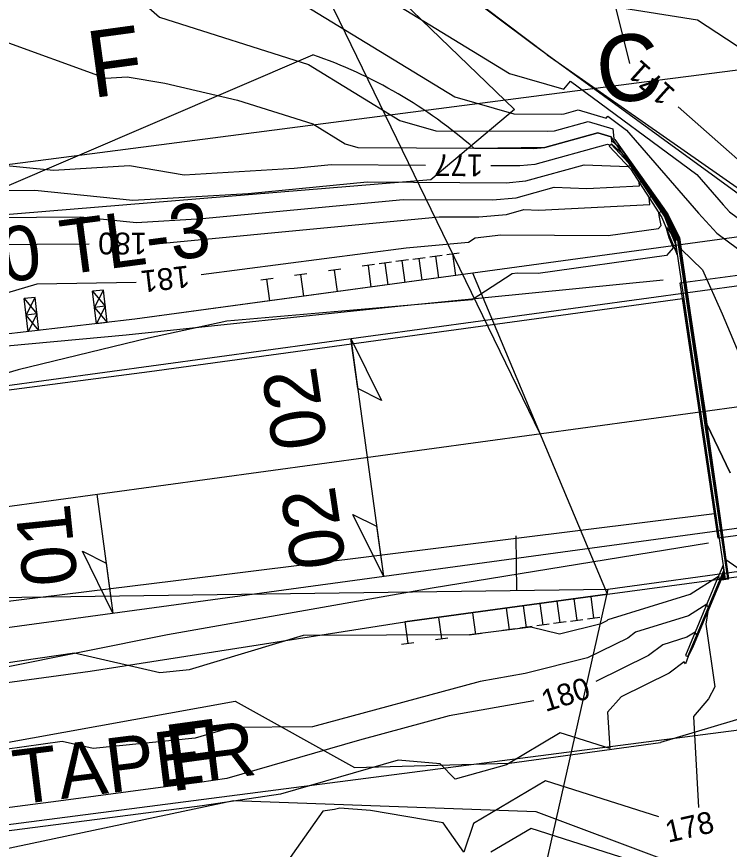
# Model space of a CAD drawing. Extents: x 2086416 to 2115205, y 575507 to 632762.
# Drawn here: x 2111454.1 to 2111519.4, y 581610 to 581686.3 of the extents above; entities that cross this region are included whole.
import ezdxf

# ---------------------------------------------------------------- set-up
doc = ezdxf.new("R2010")
doc.units = 0
for name, color, linetype in [('Default', 7, 'Continuous'), ('DTM Contours Major', 7, 'Continuous'), ('DTM Contours Major Text', 7, 'Continuous'), ('DTM Contours Minor', 7, 'Continuous'), ('DTM Contours Minor Text', 7, 'Continuous'), ('Exist Guardrail', 7, 'Continuous'), ('Exist Hydro Stream or Body of Water', 7, 'Continuous'), ('Exist Right of Way Line', 7, 'Continuous'), ('Exist Roads EOP', 7, 'Continuous'), ('Exist Structure Major Bridge WW', 7, 'Continuous'), ('Exist Structure Major Deck Tunnel Box Culvert', 7, 'Continuous'), ('Exist Vegetation Woods Line', 7, 'Continuous'), ('Prop Horizontal Alignment', 7, 'Continuous'), ('Prop Horizontal Alignment Station Label', 7, 'Continuous'), ('Prop Roadway Bridge', 7, 'Continuous'), ('Prop SS Cut Line', 7, 'Continuous'), ('Prop SS Cut Text', 7, 'Continuous'), ('Prop SS Fill Line', 7, 'Continuous'), ('Prop SS Fill Text', 7, 'Continuous')]:
    doc.layers.add(name, color=color, linetype=linetype)

msp = doc.modelspace()

# ---------------------------------------------------------------- linework, layer by layer
at = {"layer": 'Default'}
for p, q in [((2111430.061, 581649.328), (2112312.029, 581769.688)), ((2111433.036, 581627.53), (2112315.004, 581747.89)), ((2111508.232, 581633.802), (2112048.04, 581707.887)), ((2111493.061, 581664.401), (2111491.926, 581664.246)), ((2111492.764, 581662.342), (2111492.494, 581664.324)), ((2111494.609, 581664.613), (2111493.474, 581664.458)), ((2111494.312, 581662.553), (2111494.042, 581664.535)), ((2111486.868, 581663.556), (2111485.733, 581663.401)), ((2111486.571, 581661.497), (2111486.301, 581663.479)), ((2111488.417, 581663.767), (2111487.282, 581663.613)), ((2111488.12, 581661.708), (2111487.849, 581663.69)), ((2111489.965, 581663.979), (2111488.83, 581663.824)), ((2111489.668, 581661.92), (2111489.397, 581663.901)), ((2111491.513, 581664.19), (2111490.378, 581664.035)), ((2111491.216, 581662.131), (2111490.945, 581664.113)), ((2111495.86, 581662.765), (2111464.897, 581658.539)), ((2111495.86, 581662.765), (2111477.283, 581660.229)), ((2111480.676, 581662.711), (2111479.541, 581662.556)), ((2111483.772, 581663.134), (2111482.637, 581662.979)), ((2111483.475, 581661.075), (2111483.205, 581663.056)), ((2111477.58, 581662.289), (2111476.445, 581662.134)), ((2111477.283, 581660.229), (2111477.012, 581662.211)), ((2111480.379, 581660.652), (2111480.108, 581662.634)), ((2111462.026, 581661.226), (2111461.032, 581661.11)), ((2111461.205, 581659.621), (2111462.026, 581661.226)), ((2111462.372, 581658.246), (2111462.026, 581661.226)), ((2111455.76, 581660.551), (2111454.767, 581660.436)), ((2111455.119, 581657.404), (2111454.767, 581660.436)), ((2111454.767, 581660.436), (2111455.936, 581659.035)), ((2111454.943, 581658.92), (2111455.76, 581660.551)), ((2111456.113, 581657.519), (2111455.76, 581660.551)), ((2111461.378, 581658.131), (2111461.032, 581661.11)), ((2111461.032, 581661.11), (2111462.199, 581659.736)), ((2111462.199, 581659.736), (2111461.205, 581659.621)), ((2111462.199, 581659.736), (2111461.378, 581658.131)), ((2111477.283, 581660.229), (2111464.897, 581658.539)), ((2111455.936, 581659.035), (2111454.943, 581658.92)), ((2111456.113, 581657.519), (2111454.943, 581658.92)), ((2111455.936, 581659.035), (2111455.119, 581657.404)), ((2111461.378, 581658.131), (2111461.205, 581659.621)), ((2111461.205, 581659.621), (2111462.372, 581658.246)), ((2111464.897, 581658.539), (2111415.22, 581652.809)), ((2111464.897, 581658.539), (2111418.458, 581653.145)), ((2111462.372, 581658.246), (2111461.378, 581658.131)), ((2111484.697, 581656.784), (2111487.672, 581634.986)), ((2111461.414, 581642.504), (2111462.902, 581631.605)), ((2111499.906, 581633.689), (2111499.838, 581638.688)), ((2110974.978, 581626.555), (2111508.232, 581633.802)), ((2111508.232, 581633.802), (2111499.619, 581595.563)), ((2111489.638, 581630.796), (2111508.215, 581633.332)), ((2111508.215, 581633.332), (2111489.638, 581630.796)), ((2111506.667, 581633.12), (2111506.938, 581631.139)), ((2111500.475, 581632.275), (2111500.745, 581630.294)), ((2111502.023, 581632.487), (2111502.293, 581630.505)), ((2111503.571, 581632.698), (2111503.841, 581630.716)), ((2111505.119, 581632.909), (2111505.389, 581630.928)), ((2111495.83, 581631.642), (2111496.101, 581629.66)), ((2111498.926, 581632.064), (2111499.197, 581630.082)), ((2111460.813, 581626.274), (2111489.638, 581630.796)), ((2111460.813, 581626.274), (2111489.638, 581630.796)), ((2111489.638, 581630.796), (2111489.908, 581628.815)), ((2111492.734, 581631.219), (2111493.004, 581629.237)), ((2111504.409, 581630.794), (2111503.274, 581630.639)), ((2111505.957, 581631.005), (2111504.822, 581630.85)), ((2111507.505, 581631.216), (2111506.37, 581631.061)), ((2111499.764, 581630.16), (2111498.629, 581630.005)), ((2111501.312, 581630.371), (2111500.177, 581630.216)), ((2111502.861, 581630.582), (2111501.726, 581630.428)), ((2111493.572, 581629.315), (2111492.437, 581629.16)), ((2111496.668, 581629.737), (2111495.533, 581629.582)), ((2111490.475, 581628.892), (2111489.34, 581628.737)), ((2111433.712, 581622.576), (2111460.813, 581626.274)), ((2111433.712, 581622.576), (2111460.813, 581626.274))]:
    msp.add_line(p, q, dxfattribs=at)
for points in [[(2111484.697, 581656.784), (2111487.49, 581651.109), (2111485.323, 581652.201)], [(2111487.672, 581634.986), (2111484.879, 581640.66), (2111487.047, 581639.568)], [(2111462.902, 581631.605), (2111460.109, 581637.28), (2111462.276, 581636.188)]]:
    msp.add_lwpolyline(points, close=True, dxfattribs=at)
at = {"layer": 'DTM Contours Major'}
for points in [[(2111465.19, 581688.009), (2111467.154, 581686.234), (2111480.824, 581681.896), (2111489.192, 581676.776), (2111492.494, 581675.828), (2111502.699, 581675.773), (2111503.352, 581675.831), (2111506.429, 581676.686), (2111508.704, 581676.004), (2111508.773, 581675.108), (2111508.784, 581675.119), (2111508.875, 581675.036), (2111513.354, 581668.687), (2111513.757, 581668.107), (2111514.768, 581666.071), (2111514.785, 581666.034), (2111514.789, 581666.034), (2111514.946, 581664.979), (2111516.9, 581663.081), (2111518.722, 581659.055), (2111520.566, 581654.612)], [(2111466.726, 581665.442), (2111466.87, 581665.45), (2111492.781, 581667.943), (2111496.417, 581667.924), (2111498.953, 581668.15), (2111500.543, 581668.591), (2111501.91, 581668.535), (2111512.084, 581669.069), (2111512.018, 581669.692), (2111512.151, 581669.76), (2111512.231, 581669.823), (2111513.49, 581668.014), (2111513.7, 581667.591), (2111514.529, 581665.844), (2111514.698, 581665.87), (2111515.075, 581663.328), (2111515.596, 581659.884), (2111518.365, 581641.142), (2111518.823, 581637.868), (2111519.166, 581635.474), (2111519.272, 581634.752), (2111519.14, 581634.732), (2111518.801, 581634.678), (2111518.738, 581635.071), (2111516.9, 581630.641), (2111516.405, 581629.626), (2111516.266, 581629.772), (2111516.238, 581629.874), (2111515.472, 581629.388), (2111513.263, 581628.698), (2111511.967, 581627.718), (2111507.15, 581625.341)], [(2111362.56, 581651.297), (2111363.859, 581651.417), (2111367.3, 581652.098), (2111378.59, 581655.678), (2111384.736, 581656.959), (2111410.782, 581663.456), (2111412.038, 581663.856), (2111412.764, 581664.298), (2111416.283, 581665.011), (2111422.788, 581665.196), (2111444.213, 581665.517), (2111445.076, 581665.479), (2111446.412, 581665.364), (2111460.735, 581665.466)], [(2111501.468, 581623.557), (2111493.699, 581622.176), (2111485.498, 581619.952), (2111473.32, 581616.448), (2111470.815, 581616.065), (2111467.705, 581615.666), (2111457.917, 581614.372), (2111451.074, 581613.494), (2111428.1, 581610.449), (2111427.715, 581610.257), (2111423.838, 581609.834), (2111421.598, 581608.92), (2111416.907, 581607.541), (2111403.297, 581606.115)]]:
    msp.add_lwpolyline(points, dxfattribs=at)
at = {"layer": 'DTM Contours Minor'}
for points in [[(2111486.148, 581695.197), (2111501.555, 581683.631), (2111502.551, 581682.906), (2111502.693, 581682.796), (2111520.383, 581670.408), (2111523.452, 581667.816), (2111524.362, 581664.197), (2111524.453, 581663.922), (2111526.096, 581659.621), (2111528.651, 581652.847), (2111528.944, 581652.371), (2111541.304, 581641.187), (2111541.341, 581641.176), (2111541.352, 581641.177), (2111542.435, 581641.236), (2111542.834, 581640.502), (2111546.363, 581633.993), (2111548.886, 581629.315), (2111549.076, 581629.046), (2111561.223, 581607.233)], [(2111480.077, 581692.793), (2111499.229, 581681.074), (2111504.206, 581679.645), (2111504.81, 581680.373), (2111516.403, 581671.803), (2111518.792, 581669.045), (2111519.393, 581668.38), (2111520.086, 581667.875), (2111521.845, 581666.467), (2111522.333, 581664.419), (2111525.28, 581656.47), (2111526.841, 581652.331), (2111530.35, 581646.62), (2111535.812, 581641.677), (2111538.872, 581640.719), (2111540.061, 581639.915), (2111540.925, 581638.611), (2111546.88, 581628.212), (2111548.864, 581619.855), (2111549.576, 581618.418), (2111549.677, 581617.246), (2111553.4, 581604.739), (2111553.764, 581604.049), (2111566.508, 581587.068)], [(2111480.45, 581687.344), (2111494.211, 581678.925), (2111499.639, 581677.366), (2111503.956, 581677.343), (2111504.232, 581677.368), (2111505.534, 581677.729), (2111508.072, 581676.968), (2111508.234, 581677.164), (2111509.952, 581675.894), (2111516.555, 581668.27), (2111518.215, 581666.433), (2111520.131, 581665.036)], [(2111557.832, 581661.464), (2111555.517, 581665.512), (2111555.366, 581667.475), (2111555.158, 581669.318), (2111552.728, 581668.071), (2111549.514, 581667.794), (2111543.479, 581666.564), (2111541.674, 581668.031), (2111535.656, 581672.428), (2111532.643, 581674.521), (2111531.716, 581675.137), (2111527.674, 581678.306), (2111522.747, 581681.842), (2111516.457, 581685.95), (2111508.951, 581687.161), (2111510.218, 581682.003)], [(2111452.292, 581684.247), (2111462.234, 581680.656), (2111464.205, 581680.777), (2111467.66, 581680.202), (2111474.313, 581678.633), (2111481.198, 581676.448), (2111484.174, 581674.627), (2111485.348, 581674.29), (2111501.443, 581674.203), (2111502.472, 581674.295), (2111507.325, 581675.643), (2111508.552, 581675.275), (2111508.589, 581674.792), (2111508.679, 581674.876), (2111509.4, 581674.214), (2111512.43, 581669.92), (2111513.704, 581668.089), (2111514.554, 581666.375), (2111514.734, 581665.996), (2111514.771, 581666.001), (2111515.788, 581659.146), (2111517.192, 581649.853), (2111517.219, 581649.672), (2111517.321, 581648.942), (2111519.439, 581644.481)], [(2111514.671, 581678.008), (2111524.783, 581669.107), (2111525.034, 581668.631), (2111525.265, 581666.455), (2111526.022, 581664.168), (2111526.859, 581661.975), (2111532.924, 581653.146), (2111539.358, 581647.32), (2111539.946, 581647.287), (2111543.107, 581641.379), (2111543.325, 581640.975), (2111552.535, 581627.92), (2111554.709, 581624.016), (2111564.464, 581607.913)], [(2111497.534, 581672.648), (2111500.186, 581672.634), (2111501.592, 581672.759), (2111508.221, 581674.6), (2111508.4, 581674.547), (2111508.405, 581674.476), (2111508.575, 581674.633), (2111509.925, 581673.393), (2111511.505, 581671.153), (2111513.65, 581668.07), (2111514.341, 581666.679), (2111514.683, 581665.958), (2111514.753, 581665.969), (2111515.61, 581660.191), (2111516.793, 581652.361), (2111517.506, 581647.539), (2111518.546, 581640.1), (2111519.06, 581636.514), (2111521.067, 581635.109), (2111522.669, 581626.555), (2111523.048, 581624.166), (2111524.233, 581621.711), (2111524.91, 581607.809)], [(2111449.186, 581670.321), (2111455.738, 581670.367), (2111464.732, 581669.45), (2111475.3, 581670.085), (2111486.182, 581671.132), (2111498.93, 581671.064), (2111500.713, 581671.222), (2111506.079, 581672.713), (2111510.111, 581672.547), (2111510.129, 581672.563), (2111510.308, 581672.702), (2111510.451, 581672.571), (2111510.581, 581672.386), (2111513.597, 581668.051), (2111514.127, 581666.983), (2111514.631, 581665.92), (2111514.734, 581665.936), (2111515.431, 581661.237), (2111516.394, 581654.868), (2111517.792, 581645.407), (2111518.638, 581639.356), (2111519.272, 581634.932), (2111519.301, 581634.737), (2111519.265, 581634.732), (2111518.641, 581634.633), (2111518.631, 581634.695), (2111517.409, 581631.75), (2111517.204, 581630.599), (2111518.04, 581624.855), (2111517.471, 581623.738), (2111516.08, 581622.135), (2111516.553, 581613.779)], [(2111451.554, 581672.806), (2111457.455, 581672.204), (2111464.428, 581672.63), (2111469.437, 581671.797), (2111479.516, 581672.403), (2111482.882, 581672.727), (2111491.534, 581672.68)], [(2111447.799, 581667.842), (2111459.922, 581667.929), (2111465.054, 581667.406), (2111471.085, 581667.768), (2111489.481, 581669.538), (2111497.673, 581669.494), (2111499.833, 581669.686), (2111503.311, 581670.652), (2111506.303, 581670.529), (2111511.15, 581670.783), (2111511.119, 581671.08), (2111511.182, 581671.113), (2111511.324, 581671.223), (2111513.543, 581668.032), (2111513.913, 581667.287), (2111514.58, 581665.882), (2111514.716, 581665.903), (2111515.253, 581662.283), (2111515.995, 581657.376), (2111518.079, 581643.275), (2111518.731, 581638.612), (2111519.219, 581635.203), (2111519.286, 581634.745), (2111519.203, 581634.732), (2111518.721, 581634.656), (2111518.684, 581634.883), (2111516.064, 581628.567), (2111515.605, 581627.625), (2111515.364, 581626.964), (2111515.221, 581627.138), (2111513.863, 581626.111), (2111509.449, 581623.933), (2111508.219, 581622.515), (2111508.407, 581619.183), (2111503.877, 581620.626), (2111498.95, 581617.702), (2111494.253, 581616.382), (2111492.88, 581617.804), (2111489.025, 581618.122), (2111478.259, 581615.024), (2111471.081, 581613.927), (2111462.169, 581612.782), (2111458.615, 581612.313), (2111444.604, 581610.516)], [(2111470.971, 581662.653), (2111489.767, 581665.106), (2111495.482, 581665.607), (2111496.094, 581666.005), (2111498.446, 581666.298), (2111508.265, 581666.219), (2111512.889, 581666.862), (2111513.119, 581667.125), (2111512.943, 581668.065), (2111512.918, 581668.303), (2111513.12, 581668.408), (2111513.139, 581668.423), (2111513.437, 581667.995), (2111513.486, 581667.895), (2111514.477, 581665.806), (2111514.68, 581665.837), (2111514.897, 581664.374), (2111515.196, 581662.392), (2111518.652, 581639.01), (2111518.916, 581637.124), (2111519.113, 581635.746), (2111519.258, 581634.759), (2111519.078, 581634.732), (2111518.882, 581634.701), (2111518.792, 581635.26), (2111517.736, 581632.715), (2111517.451, 581632.131), (2111517.372, 581632.216), (2111517.309, 581632.44), (2111515.626, 581631.372), (2111510.771, 581629.854), (2111510.07, 581629.324), (2111506.387, 581627.507), (2111500.669, 581626.069), (2111496.529, 581625.334), (2111481.177, 581621.169), (2111473.746, 581621.131), (2111470.433, 581620.135), (2111461.073, 581619.199), (2111458.251, 581619.843), (2111453.021, 581619.09)], [(2111514.426, 581665.768), (2111514.076, 581666.505), (2111514.07, 581666.377), (2111513.681, 581666.938), (2111513.593, 581666.892), (2111513.813, 581666.05), (2111514.217, 581665.091), (2111513.834, 581664.627), (2111513.623, 581664.386), (2111501.864, 581662.752), (2111499.925, 581662.768), (2111499.461, 581662.71), (2111495.816, 581660.338), (2111473.348, 581658.369), (2111466.15, 581656.804), (2111454.207, 581653.913), (2111447.466, 581651.924)], [(2111444.88, 581625.862), (2111459.383, 581627.95), (2111467.209, 581626.166), (2111469.917, 581626.437), (2111480.37, 581629.578), (2111495.562, 581629.657), (2111501.182, 581630.34), (2111503.81, 581629.699), (2111507.617, 581630.655), (2111508.174, 581630.93), (2111508.279, 581631.01), (2111515.78, 581633.356), (2111518.381, 581635.005), (2111518.477, 581634.659), (2111518.498, 581634.637), (2111518.572, 581634.788), (2111518.845, 581635.448), (2111518.962, 581634.724), (2111519.015, 581634.732), (2111519.244, 581634.766), (2111519.06, 581636.017), (2111519.008, 581636.38), (2111518.938, 581636.877), (2111514.797, 581664.899), (2111514.718, 581665.42), (2111514.661, 581665.804), (2111514.426, 581665.768)], [(2111269.918, 581624.058), (2111270.71, 581624.172), (2111275.888, 581625.032), (2111295.143, 581628.295), (2111310.242, 581631.559), (2111319.393, 581633.414), (2111333.072, 581637.242), (2111339.352, 581639.052), (2111342.163, 581639.082), (2111342.18, 581639.377), (2111344.603, 581639.49), (2111345.711, 581639.592), (2111368.058, 581644.016), (2111371.035, 581644.959), (2111390.012, 581648.914), (2111399.542, 581651.291), (2111412.87, 581655.543), (2111414.88, 581656.764), (2111417.768, 581657.244), (2111425.188, 581659.107), (2111446.75, 581659.064), (2111455.965, 581661.783), (2111465.015, 581661.958)], [(2111512.897, 581612.943), (2111502.542, 581616.244), (2111495.925, 581612.318), (2111495.047, 581609.681), (2111493.145, 581612.369), (2111486.486, 581613.505), (2111483.671, 581613.737), (2111483.198, 581613.6), (2111482.119, 581613.436), (2111472.626, 581599.987), (2111469.34, 581599.165), (2111466.838, 581596.068), (2111463.884, 581593.537), (2111423.2, 581580.097), (2111421.166, 581578.021), (2111413.921, 581573.833), (2111415.71, 581582.768), (2111413.83, 581586.352), (2111407.094, 581599.119), (2111404.077, 581600.927), (2111385.483, 581590.707), (2111395.032, 581602.545), (2111389.517, 581602.876), (2111380.322, 581601.494)], [(2111519.094, 581606.16), (2111501.206, 581611.862), (2111497.531, 581609.681)]]:
    msp.add_lwpolyline(points, dxfattribs=at)
at = {"layer": 'Exist Guardrail'}
for points in [[(2111362.575, 581648.007), (2111389.492, 581650.444), (2111420.347, 581653.094), (2111464.121, 581657.103), (2111488.988, 581659.753), (2111513.299, 581662.166)], [(2111517.463, 581638.01), (2111492.131, 581633.892), (2111467.882, 581629.628), (2111437.303, 581623.465), (2111412.521, 581619.342), (2111387.75, 581616.146), (2111369.251, 581613.832), (2111317.742, 581607.802)]]:
    msp.add_lwpolyline(points, dxfattribs=at)
at = {"layer": 'Exist Hydro Stream or Body of Water'}
msp.add_lwpolyline([(2111591.587, 581574.691), (2111583.513, 581582.318), (2111586.645, 581587.276), (2111586.904, 581588.764), (2111586.51, 581589.985), (2111561.568, 581606.344), (2111549.003, 581629.07), (2111542.467, 581641.26), (2111541.348, 581641.183), (2111528.816, 581652.894), (2111524.362, 581663.908), (2111523.315, 581667.748), (2111502.682, 581682.779), (2111481.94, 581698.457), (2111468.579, 581724.282), (2111462.999, 581737.482)], dxfattribs=at)
at = {"layer": 'Exist Right of Way Line'}
for points in [[(2111371.804, 581662.16), (2111512.522, 581680.421)], [(2111379.525, 581602.659), (2111520.243, 581620.919)]]:
    msp.add_lwpolyline(points, dxfattribs=at)
msp.add_arc((2108326.546, 606231.499), 24756.937, 277.3939111, 277.8562149, dxfattribs=at)
at = {"layer": 'Exist Roads EOP'}
for points in [[(2111417.782, 581647.422), (2111417.782, 581647.422), (2111466.254, 581653.757), (2111515.092, 581660.442), (2111516.542, 581650.631)], [(2111419.52, 581628.553), (2111419.52, 581628.553), (2111468.663, 581634.583), (2111518.005, 581640.729), (2111516.542, 581650.631)]]:
    msp.add_lwpolyline(points, dxfattribs=at)
at = {"layer": 'Exist Structure Major Bridge WW'}
for points in [[(2111514.582, 581664.44), (2111514.435, 581665.473), (2111514.083, 581666.345), (2111513.42, 581667.989), (2111510.498, 581672.497), (2111508.557, 581674.592), (2111508.374, 581674.422), (2111510.3, 581672.343), (2111513.197, 581667.873), (2111513.851, 581666.252), (2111514.582, 581664.44)], [(2111514.655, 581665.792), (2111514.408, 581665.755), (2111518.992, 581634.732), (2111519.239, 581634.769), (2111514.655, 581665.792)], [(2111518.864, 581635.514), (2111518.791, 581635.988), (2111518.239, 581634.666), (2111515.343, 581627.732), (2111515.574, 581627.636), (2111518.47, 581634.57), (2111518.864, 581635.514)]]:
    msp.add_lwpolyline(points, dxfattribs=at)
at = {"layer": 'Exist Structure Major Deck Tunnel Box Culvert'}
msp.add_lwpolyline([(2111518.338, 581638.473), (2111518.005, 581640.729), (2111516.542, 581650.631), (2111515.092, 581660.442), (2111514.879, 581661.883), (2111532.718, 581664.281), (2111549.455, 581666.531), (2111567.238, 581668.922), (2111567.482, 581667.278), (2111568.946, 581657.382), (2111570.384, 581647.665), (2111570.703, 581645.511), (2111552.911, 581643.12), (2111536.107, 581640.862), (2111518.338, 581638.473)], dxfattribs=at)
at = {"layer": 'Exist Vegetation Woods Line'}
for points in [[(2111452.102, 581736.219), (2111479.268, 581697.501), (2111499.678, 581677.784), (2111492.037, 581671.336), (2111416.636, 581665.128), (2111367.277, 581660.929), (2111318.174, 581654.198), (2111268.317, 581650.615), (2111220.664, 581649.448), (2111173.288, 581649.119), (2111125.979, 581651.571), (2111078.275, 581655.724), (2111059.793, 581657.645)], [(2111257.868, 581581.404), (2111333.104, 581590.969), (2111406.178, 581600.069), (2111473.936, 581614.42), (2111501.631, 581613.416), (2111525.035, 581604.65), (2111555.787, 581590.729), (2111597.414, 581531.022), (2111635.4, 581485.12), (2111692.38, 581438.808), (2111736.925, 581397.696), (2111757.961, 581379.063)]]:
    msp.add_lwpolyline(points, dxfattribs=at)
at = {"layer": 'Prop Horizontal Alignment'}
msp.add_line((2111431.548, 581638.429), (2112404.465, 581771.2), dxfattribs=at)
at = {"layer": 'Prop Horizontal Alignment Station Label'}
msp.add_line((2111502.038, 581648.048), (2111433.298, 581789.658), dxfattribs=at)
at = {"layer": 'Prop Roadway Bridge'}
for p, q in [((2111585.034, 581674.934), (2111495.86, 581662.765)), ((2111508.215, 581633.332), (2111495.86, 581662.765)), ((2111508.215, 581633.332), (2111597.389, 581645.501))]:
    msp.add_line(p, q, dxfattribs=at)
at = {"layer": 'Prop SS Cut Line'}
for p, q in [((2111507.325, 581675.643), (2111502.472, 581674.295)), ((2111508.552, 581675.275), (2111507.325, 581675.643)), ((2111514.771, 581666.001), (2111508.552, 581675.275)), ((2111502.472, 581674.295), (2111496.001, 581674.207)), ((2111517.321, 581648.942), (2111514.771, 581666.001)), ((2111519.439, 581644.481), (2111517.321, 581648.942)), ((2111522.497, 581622.577), (2111513.072, 581619.756))]:
    msp.add_line(p, q, dxfattribs=at)
at = {"layer": 'Prop SS Fill Line'}
for p, q in [((2111419.256, 581656.202), (2111481.214, 581682.795)), ((2111424.759, 581614.575), (2111474.094, 581623.547)), ((2111499.224, 581617.866), (2111513.072, 581619.756)), ((2111485.015, 581617.465), (2111499.224, 581617.866))]:
    msp.add_line(p, q, dxfattribs=at)
msp.add_lwpolyline([(2111474.094, 581623.547), (2111485.015, 581617.465)], dxfattribs=at)
msp.add_arc((2111466.549, 581640.517), 44.749, 48.8396, 70.86984, dxfattribs=at)

# ---------------------------------------------------------------- texts
at = {"layer": 'Default'}
for s, rotation, p in [('GRAU 350 TL-3', 7.47611, (2111424.522, 581658.168)), ('02', 98.4844, (2111482.566, 581646.994)), ('02', 98.4844, (2111484.281, 581636.049)), ('01', 95.93956, (2111459.691, 581634.356)), ('50:1 TAPER', 7.11815, (2111439.329, 581612.198))]:
    msp.add_text(s, height=5, rotation=rotation, dxfattribs=at).set_placement(p)
at = {"layer": 'DTM Contours Major Text'}
for rotation, p in [(179.76623, (2111466.014, 581666.478)), (17.43289, (2111502.531, 581622.532))]:
    msp.add_text('180', height=2, rotation=rotation, dxfattribs=at).set_placement(p)
at = {"layer": 'DTM Contours Minor Text'}
for s, rotation, p in [('171', 138.09884, (2111514.528, 581679.441)), ('177', 179.69151, (2111496.815, 581673.652)), ('181', 186.65941, (2111469.804, 581663.483)), ('178', 12.8825, (2111513.76, 581610.55))]:
    msp.add_text(s, height=2, rotation=rotation, dxfattribs=at).set_placement(p)
at = {"layer": 'Prop SS Cut Text'}
msp.add_text('C', height=6.104, rotation=7.77101, dxfattribs=at).set_placement((2111507.614, 581678.163))
at = {"layer": 'Prop SS Fill Text'}
for p in [(2111461.013, 581678.814), (2111468.165, 581615.239)]:
    msp.add_text('F', height=6.104, rotation=7.77101, dxfattribs=at).set_placement(p)

doc.saveas('drawing.dxf')
